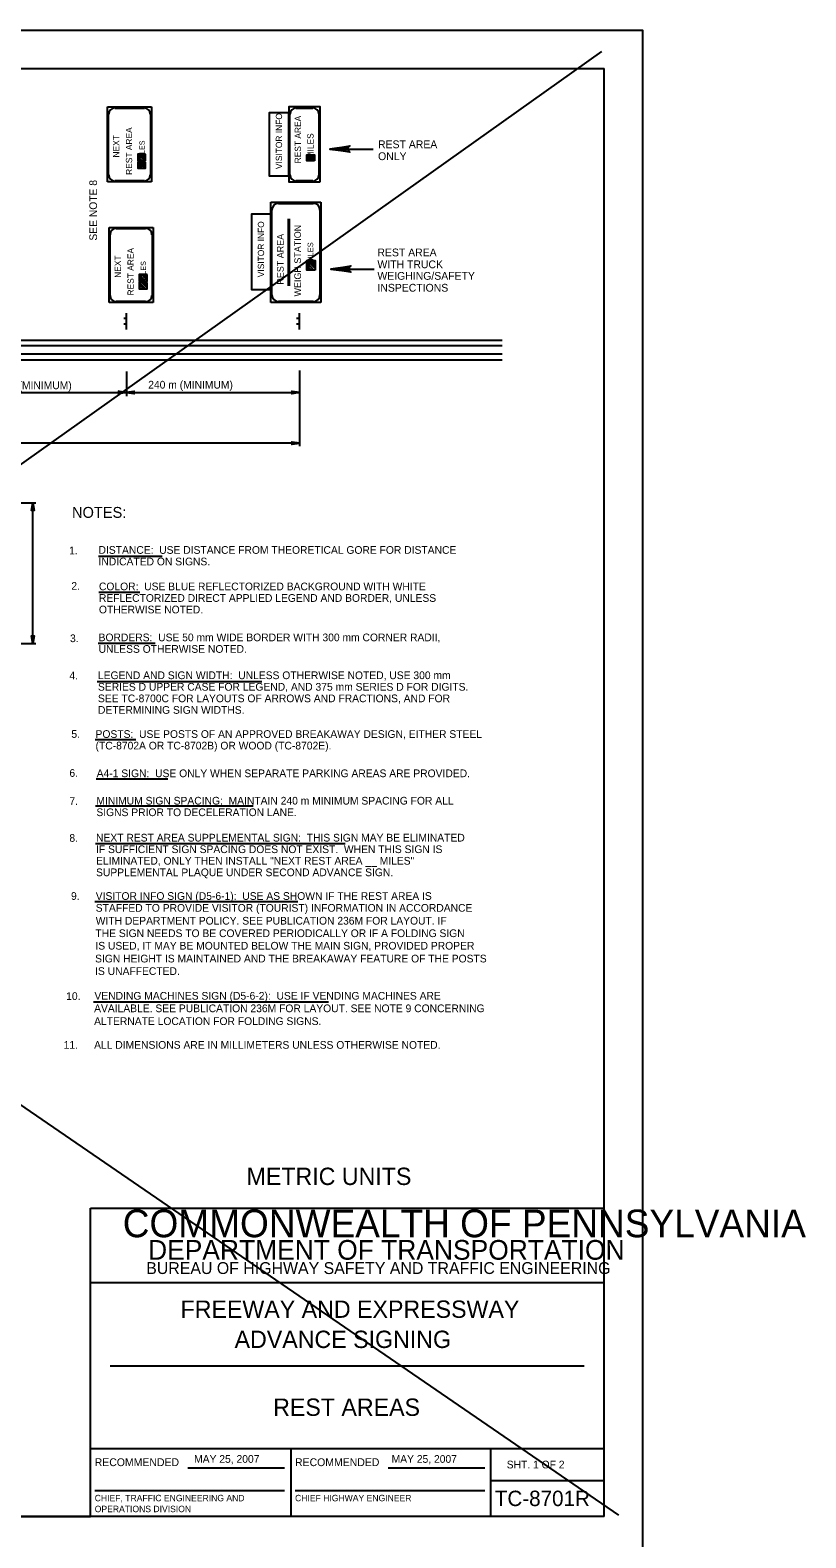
# Model space of a CAD drawing. Extents: x 649604 to 650509, y 298458 to 299646.
# Drawn here: x 650207 to 650509, y 299058 to 299646 of the extents above; entities that cross this region are included whole.
import ezdxf

# ---------------------------------------------------------------- set-up
doc = ezdxf.new("R2010")
doc.units = 0
for name, color, linetype in [('1', 7, 'Continuous'), ('2', 7, 'Continuous'), ('3', 7, 'Continuous'), ('PLT-BNDY', 7, 'Continuous')]:
    doc.layers.add(name, color=color, linetype=linetype)

# ---------------------------------------------------------------- blocks, each defined once
blk = doc.blocks.new('RARROW')
at = {"layer": '3'}
blk.add_lwpolyline([(-2.2695, 0.285), (-2.184875, 0.12075), (0, 0), (-2.2695, 0.285), (-2.38575, 0.384625), (0, 0), (-2.183125, -0.108), (-2.262875, -0.2705), (0, 0), (-2.38575, -0.379125), (-2.262875, -0.2705)], dxfattribs=at)

msp = doc.modelspace()

# ---------------------------------------------------------------- linework, layer by layer
at = {"layer": '1'}
for p, q in [((649644.31, 299630.63), (650430.31, 299630.63)), ((650430.31, 299066.63), (650430.31, 299630.63)), ((650230.31, 299066.63), (650230.31, 299186.63)), ((650230.31, 299186.63), (650430.31, 299186.63)), ((650430.31, 299157.63), (650230.31, 299157.63)), ((650238.06, 299125.31), (650422.56, 299125.31)), ((650230.31, 299093), (650430.31, 299093)), ((650308.31, 299093), (650308.31, 299066.63)), ((650386.19, 299066.63), (650386.19, 299093)), ((650268.24, 299085.57), (650305.87, 299085.57)), ((650346.24, 299085.57), (650383.87, 299085.57)), ((650386.19, 299080.63), (650430.31, 299080.63)), ((650231.99, 299076.68), (650305.87, 299076.68)), ((650309.99, 299076.68), (650383.87, 299076.68)), ((650430.31, 299066.63), (649644.31, 299066.63)), ((649644.31, 299066.63), (650230.31, 299066.63))]:
    msp.add_line(p, q, dxfattribs=at)
at = {"layer": '2'}
for p, q in [((650429.28, 299637.34), (649624.76, 299064.89)), ((649618.13, 299628.5), (650435.92, 299067.1)), ((650236.94, 299586.5), (650236.94, 299615.75)), ((650236.94, 299615.75), (650254.06, 299615.75)), ((650237.31, 299589.25), (650237.31, 299612.88)), ((650239.81, 299615.25), (650251.31, 299615.25)), ((650253.69, 299612.88), (650253.69, 299589.25)), ((650254.06, 299615.75), (650254.06, 299586.5)), ((650310.31, 299615.25), (650316.94, 299615.25)), ((650323.56, 299599.25), (650340.44, 299599.25)), ((650254.06, 299586.5), (650236.94, 299586.5)), ((650251.31, 299586.88), (650239.81, 299586.88)), ((650300.56, 299539.5), (650300.56, 299578.63)), ((650303.56, 299578.13), (650317.06, 299578.13)), ((650320.06, 299578.63), (650320.06, 299539.5)), ((650300.94, 299542.5), (650300.94, 299575.63)), ((650307.44, 299546), (650307.44, 299572.13)), ((650307.56, 299546), (650307.56, 299572.13)), ((650307.69, 299546), (650307.69, 299572.13)), ((650307.81, 299546), (650307.81, 299572.13)), ((650307.81, 299546), (650307.81, 299572.13)), ((650319.69, 299575.63), (650319.69, 299542.5)), ((650237.56, 299539.5), (650237.56, 299568.75)), ((650237.56, 299568.75), (650254.69, 299568.75)), ((650238.06, 299542.25), (650238.06, 299565.88)), ((650240.31, 299568.38), (650251.81, 299568.38)), ((650254.31, 299565.88), (650254.31, 299542.25)), ((650254.69, 299568.75), (650254.69, 299539.5)), ((650323.94, 299552.5), (650340.81, 299552.5)), ((650254.69, 299539.5), (650237.56, 299539.5)), ((650251.81, 299539.88), (650240.31, 299539.88)), ((650244.31, 299529), (650244.31, 299535.38)), ((650311.69, 299529), (650311.69, 299535.38)), ((650244.31, 299533.25), (650243.31, 299533.25)), ((650244.31, 299531.13), (650243.31, 299531.13)), ((650311.69, 299533.25), (650310.56, 299533.25)), ((650311.69, 299531.13), (650310.56, 299531.13)), ((649946.56, 299524.88), (650390.69, 299524.88)), ((650330.44, 299524.88), (650330.44, 299524.88)), ((649664.19, 299522.75), (650390.69, 299522.75)), ((649664.19, 299519.5), (650390.69, 299519.5)), ((649664.19, 299517.25), (650390.69, 299517.25)), ((650244.31, 299512.63), (650244.31, 299503)), ((650311.69, 299513), (650311.69, 299483.5)), ((650176.94, 299504.5), (650244.31, 299504.5)), ((650244.31, 299504.5), (650311.69, 299504.5)), ((650311.69, 299484.75), (649881.31, 299484.75)), ((650180.48, 299461.5), (650209, 299461.5)), ((650207.88, 299406.63), (650207.88, 299461.5)), ((650233.42, 299440.75), (650258.31, 299440.75)), ((650233.57, 299426.66), (650249.5, 299426.66)), ((650180.48, 299406.63), (650209, 299406.63)), ((650233.32, 299406.8), (650255.5, 299406.8)), ((650232.96, 299391.93), (650297, 299391.93)), ((650232.22, 299369.29), (650247.93, 299369.29)), ((650232.57, 299353.98), (650260.48, 299353.98)), ((650232.31, 299343.4), (650293.65, 299343.4)), ((650232.3, 299328.76), (650329.5, 299328.76)), ((650232.07, 299306.17), (650311.03, 299306.17)), ((650231.47, 299267.05), (650322.98, 299267.05))]:
    msp.add_line(p, q, dxfattribs=at)
for points in [[(650307.56, 299588.88), (650307.56, 299613.38), (650299.94, 299613.38), (650299.94, 299588.88)], [(650319.81, 299586.5), (650319.81, 299615.75), (650307.56, 299615.75), (650307.56, 299586.5)], [(650251.81, 299597.25), (650248.81, 299597.25), (650248.81, 299594.88), (650251.81, 299594.88)], [(650251.81, 299594.25), (650248.81, 299594.25), (650248.81, 299591.88), (650251.81, 299591.88)], [(650317.56, 299594.75), (650314.56, 299594.75), (650314.56, 299597), (650317.56, 299597)], [(650300.56, 299544.63), (650300.56, 299574), (650293.06, 299574), (650293.06, 299544.63)], [(650317.81, 299552.13), (650314.56, 299552.13), (650314.56, 299555.88), (650317.81, 299555.88)], [(650252.44, 299550.38), (650249.31, 299550.38), (650249.31, 299547.88), (650252.44, 299547.88)], [(650252.44, 299547.38), (650249.31, 299547.38), (650249.31, 299544.88), (650252.44, 299544.88)]]:
    msp.add_lwpolyline(points, close=True, dxfattribs=at)
for points in [[(650307.94, 299589.25), (650307.94, 299612.88)], [(650319.31, 299612.88), (650319.31, 299589.25)], [(650331.06, 299598.38), (650330.69, 299599), (650323.56, 299599.25), (650331.06, 299598.38), (650331.31, 299598.13), (650323.56, 299599.25), (650330.69, 299599.75), (650330.94, 299600.25), (650323.56, 299599.25), (650331.31, 299600.5), (650330.94, 299600.25)], [(650251.31, 299594.88), (650248.81, 299597.25)], [(650250.31, 299594.88), (650248.81, 299596.5)], [(650249.44, 299594.88), (650248.81, 299595.75)], [(650251.31, 299591.88), (650248.81, 299594.25)], [(650251.81, 299592.13), (650249.56, 299594.25)], [(650251.81, 299595.13), (650249.69, 299597.25)], [(650251.81, 299596), (650250.44, 299597.25)], [(650251.81, 299592.88), (650250.44, 299594.25)], [(650251.81, 299597), (650251.44, 299597.25)], [(650251.81, 299593.88), (650251.44, 299594.25)], [(650316.81, 299594.75), (650314.56, 299597)], [(650316.31, 299594.75), (650314.56, 299596.5)], [(650315.81, 299594.75), (650314.56, 299596)], [(650315.44, 299594.75), (650314.56, 299595.63)], [(650314.94, 299594.75), (650314.56, 299595.13)], [(650317.19, 299594.75), (650314.81, 299597)], [(650317.56, 299594.88), (650315.19, 299597)], [(650317.56, 299595.38), (650315.69, 299597)], [(650317.56, 299595.88), (650316.19, 299597)], [(650317.56, 299596.25), (650316.69, 299597)], [(650317.56, 299596.75), (650317.06, 299597)], [(650250.31, 299591.88), (650248.81, 299593.5)], [(650249.44, 299591.88), (650248.81, 299592.5)], [(650316.94, 299586.88), (650310.31, 299586.88)], [(650300.56, 299578.63), (650302.94, 299578.63), (650305.56, 299578.63), (650307.69, 299578.63), (650309.69, 299578.63), (650312.31, 299578.63), (650314.56, 299578.63), (650315.06, 299578.63), (650317.06, 299578.63), (650317.81, 299578.63), (650320.06, 299578.63)], [(650317.81, 299552.75), (650314.56, 299555.88)], [(650317.31, 299552.13), (650314.56, 299555.13)], [(650316.44, 299552.13), (650314.56, 299554.13)], [(650315.56, 299552.13), (650314.56, 299553.25)], [(650317.81, 299553.63), (650315.44, 299555.88)], [(650317.81, 299554.5), (650316.44, 299555.88)], [(650317.81, 299555.5), (650317.31, 299555.88)], [(650331.31, 299551.63), (650331.19, 299552.13), (650323.94, 299552.5), (650331.31, 299551.63), (650331.69, 299551.38), (650323.94, 299552.5), (650331.19, 299553), (650331.31, 299553.5), (650323.94, 299552.5), (650331.69, 299553.75), (650331.31, 299553.5)], [(650251.81, 299547.88), (650249.31, 299550.38)], [(650251.06, 299547.88), (650249.31, 299549.5)], [(650250.19, 299547.88), (650249.31, 299548.75)], [(650251.81, 299544.88), (650249.31, 299547.38)], [(650252.44, 299548.25), (650250.31, 299550.38)], [(650252.44, 299545.25), (650250.31, 299547.38)], [(650252.44, 299549.13), (650251.19, 299550.38)], [(650252.44, 299546), (650251.19, 299547.38)], [(650252.44, 299549.88), (650252.06, 299550.38)], [(650252.44, 299546.88), (650252.06, 299547.38)], [(650314.56, 299552.13), (650314.56, 299552.25)], [(650251.06, 299544.88), (650249.31, 299546.5)], [(650250.19, 299544.88), (650249.31, 299545.5)], [(650320.06, 299539.5), (650300.56, 299539.5)], [(650317.06, 299539.88), (650303.56, 299539.88)]]:
    msp.add_lwpolyline(points, dxfattribs=at)
for centre, radius, start, end in [((650239.81, 299612.91), 2.44, 90, 180), ((650251.22, 299612.91), 2.44, 0, 90), ((650310.4, 299612.91), 2.44, 90, 180), ((650316.92, 299612.91), 2.44, 0, 90), ((650239.81, 299589.29), 2.44, 180, 270), ((650251.22, 299589.29), 2.44, 270, 0), ((650310.4, 299589.29), 2.44, 180, 270), ((650316.92, 299589.29), 2.44, 270, 0), ((650303.6, 299575.54), 2.61, 90, 180), ((650317.08, 299575.54), 2.61, 0, 90), ((650240.41, 299565.93), 2.44, 90, 180), ((650251.82, 299565.93), 2.44, 0, 90), ((650240.41, 299542.3), 2.44, 180, 270), ((650251.82, 299542.3), 2.44, 270, 0), ((650303.6, 299542.5), 2.61, 180, 270), ((650317.08, 299542.5), 2.61, 270, 0)]:
    msp.add_arc(centre, radius, start, end, dxfattribs=at)
at = {"layer": 'PLT-BNDY'}
msp.add_lwpolyline([(649604.31, 299645.63), (650445.31, 299645.63), (650445.31, 299051.63), (649604.31, 299051.63)], close=True, dxfattribs=at)

# ---------------------------------------------------------------- block references
at = {"layer": '2', "xscale": 1.2574347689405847, "yscale": 1.3092961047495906}
for p in [(650244.31, 299504.5), (650311.69, 299504.5), (650311.69, 299484.75)]:
    msp.add_blockref('RARROW', p, dxfattribs=at)
for p, rotation in [((650244.31, 299504.5), 180), ((650207.88, 299461.5), 89.99999999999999), ((650207.88, 299406.63), -90.00000000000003)]:
    msp.add_blockref('RARROW', p, dxfattribs=dict(at, rotation=rotation))

# ---------------------------------------------------------------- texts
at = {"layer": '1'}
for s, height, p in [('COMMONWEALTH OF PENNSYLVANIA', 10.7828, (650242.9, 299175.36)), ('DEPARTMENT OF TRANSPORTATION', 7.6837, (650252.76, 299166.61)), ('BUREAU OF HIGHWAY SAFETY AND TRAFFIC ENGINEERING', 4.6253, (650252.04, 299161.04)), ('FREEWAY AND EXPRESSWAY', 6.75, (650265.42, 299143.97)), ('ADVANCE SIGNING', 6.75, (650286.45, 299132.22)), ('REST AREAS', 6.75, (650301.47, 299105.78)), ('RECOMMENDED', 3.048, (650231.99, 299086.2)), ('RECOMMENDED', 3.048, (650309.99, 299086.2)), ('SHT. 1 OF 2', 3, (650392.4, 299085.31)), ('TC-8701R', 6, (650387.77, 299070.63)), ('CHIEF, TRAFFIC ENGINEERING AND', 2.5, (650231.99, 299072.51)), ('CHIEF HIGHWAY ENGINEER', 2.5, (650309.99, 299072.51)), ('OPERATIONS DIVISION', 2.5, (650231.99, 299068.26))]:
    msp.add_text(s, height=height, dxfattribs=at).set_placement(p)
at = {"layer": '2'}
for s, height, p in [('VISITOR INFO', 2.4443, (650304.94, 299591.5)), ('REST AREA', 2.444, (650312.31, 299593.75)), ('REST AREA', 2.443, (650246.56, 299589.25)), ('NEXT', 2.443, (650241.56, 299596)), ('   MILES', 2.035, (650251.44, 299591.88)), ('    MILES', 2.443, (650317.19, 299592)), ('SEE NOTE 8', 3, (650232.89, 299563.63)), ('VISITOR INFO', 2.4443, (650297.94, 299549.38)), ('REST AREA', 2.608, (650305.56, 299546.5)), ('WEIGH STATION', 2.6078, (650312.31, 299541.88)), ('REST AREA', 2.443, (650247.19, 299542.25)), ('  MILES', 2.174, (650317.06, 299552.63)), ('NEXT', 2.443, (650242.19, 299549.13)), ('   MILES', 2.035, (650251.94, 299544.88))]:
    msp.add_text(s, height=height, rotation=90, dxfattribs=at).set_placement(p)
for s, height, p in [('REST AREA', 3.041, (650342.31, 299599.63)), ('ONLY', 3.041, (650342.31, 299595)), ('REST AREA', 3.041, (650342.06, 299557.5)), ('WITH TRUCK', 3.041, (650342.06, 299552.88)), ('WEIGHING/SAFETY', 3.0405, (650342.06, 299548.38)), ('INSPECTIONS', 3.0405, (650342.06, 299543.75)), ('240 m (MINIMUM)', 3, (650190.06, 299505.75)), ('240 m (MINIMUM)', 3, (650252.81, 299506)), ('NOTES:', 4.25, (650223.15, 299455.63)), ('1.  ', 3, (650222, 299441.41)), ('DISTANCE:  USE DISTANCE FROM THEORETICAL GORE FOR DISTANCE', 3, (650233.47, 299441.62)), ('INDICATED ON SIGNS.', 3, (650233.47, 299437.12)), ('2.  ', 3, (650222.89, 299427.61)), ('COLOR:  USE BLUE REFLECTORIZED BACKGROUND WITH WHITE', 3, (650233.63, 299427.41)), ('REFLECTORIZED DIRECT APPLIED LEGEND AND BORDER, UNLESS', 3, (650233.63, 299422.91)), ('OTHERWISE NOTED.', 3, (650233.63, 299418.41)), ('3.  ', 3, (650222.38, 299407.21)), ('UNLESS OTHERWISE NOTED.', 3, (650233.5, 299403.05)), ('BORDERS:  USE 50 mm WIDE BORDER WITH 300 mm CORNER RADII,', 3, (650233.5, 299407.55)), ('4.', 3, (650222.13, 299392.69)), ('LEGEND AND SIGN WIDTH:  UNLESS OTHERWISE NOTED, USE 300 mm', 3, (650233.25, 299392.8)), ('SERIES D UPPER CASE FOR LEGEND, AND 375 mm SERIES D FOR DIGITS.', 3, (650233.25, 299388.3)), ('SEE TC-8700C FOR LAYOUTS OF ARROWS AND FRACTIONS, AND FOR ', 3, (650233.25, 299383.8)), ('DETERMINING SIGN WIDTHS.', 3, (650233.25, 299379.3)), ('5.  ', 3, (650222.89, 299369.93)), ('POSTS:  USE POSTS OF AN APPROVED BREAKAWAY DESIGN, EITHER STEEL', 3, (650232.31, 299369.9)), ('(TC-8702A OR TC-8702B) OR WOOD (TC-8702E).', 3, (650232.31, 299365.4)), ('6.  ', 3, (650222.14, 299354.74)), ('A4-1 SIGN:  USE ONLY WHEN SEPARATE PARKING AREAS ARE PROVIDED.', 3, (650232.75, 299354.6)), ('MINIMUM SIGN SPACING:  MAINTAIN 240 m MINIMUM SPACING FOR ALL', 3, (650232.63, 299343.93)), ('7.  ', 3, (650222.12, 299343.81)), ('SIGNS PRIOR TO DECELERATION LANE.', 3, (650232.63, 299339.43)), ('8.  ', 3, (650222.13, 299329.43)), ('NEXT REST AREA SUPPLEMENTAL SIGN:  THIS SIGN MAY BE ELIMINATED', 3, (650232.5, 299329.53)), ('ELIMINATED, ONLY THEN INSTALL "NEXT REST AREA __ MILES" ', 3, (650232.5, 299320.53)), ('IF SUFFICIENT SIGN SPACING DOES NOT EXIST.  WHEN THIS SIGN IS', 3, (650232.5, 299325.03)), ('SUPPLEMENTAL PLAQUE UNDER SECOND ADVANCE SIGN.', 3, (650232.5, 299316.03)), ('9.  ', 3, (650222.76, 299306.81)), ('VISITOR INFO SIGN (D5-6-1):  USE AS SHOWN IF THE REST AREA IS', 3, (650232.38, 299306.8)), ('WITH DEPARTMENT POLICY. SEE PUBLICATION 236M FOR LAYOUT. IF', 3, (650232.38, 299297.17)), ('STAFFED TO PROVIDE VISITOR (TOURIST) INFORMATION IN ACCORDANCE', 3, (650232.38, 299302.18)), ('THE SIGN NEEDS TO BE COVERED PERIODICALLY OR IF A FOLDING SIGN', 3, (650232.25, 299292.3)), ('IS USED, IT MAY BE MOUNTED BELOW THE MAIN SIGN, PROVIDED PROPER', 3, (650232.25, 299287.43)), ('SIGN HEIGHT IS MAINTAINED AND THE BREAKAWAY FEATURE OF THE POSTS', 3, (650232.13, 299282.43)), ('IS UNAFFECTED.', 3, (650232.13, 299277.55)), ('10.   ', 3, (650220.87, 299267.81)), ('VENDING MACHINES SIGN (D5-6-2):  USE IF VENDING MACHINES ARE', 3, (650231.88, 299267.93)), ('AVAILABLE. SEE PUBLICATION 236M FOR LAYOUT. SEE NOTE 9 CONCERNING', 3, (650231.75, 299263.05)), ('ALTERNATE LOCATION FOR FOLDING SIGNS.', 3, (650231.75, 299258.05)), ('11. ', 3, (650219.88, 299248.8)), ('ALL DIMENSIONS ARE IN MILLIMETERS UNLESS OTHERWISE NOTED.', 3, (650231.75, 299248.8)), ('METRIC UNITS', 6.75, (650291.11, 299195.72)), ('MAY 25, 2007', 3, (650270.69, 299087.49)), ('MAY 25, 2007', 3, (650347.59, 299087.49))]:
    msp.add_text(s, height=height, dxfattribs=at).set_placement(p)

doc.saveas('drawing.dxf')
